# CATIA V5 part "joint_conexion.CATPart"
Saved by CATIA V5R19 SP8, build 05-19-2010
Part number: joint_conexion
Revision: ANY
Definition: UNKNOWN
Nomenclature: 12
Source: Unknown
Bounding box of the stored display mesh (mm): x 0 to 6, y -6 to 6, z 0 to 13
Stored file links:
  D:\Documents\1_Travail\2- 2I2D\1 - Cours et TD\2- TD\3-TD Assemblage\Pompe AirMan\joint_conexion.CATPart
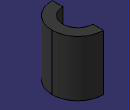
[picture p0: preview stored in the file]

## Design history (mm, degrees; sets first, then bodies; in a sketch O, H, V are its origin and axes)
Body1 "Enlèv. mat.-Extru.1" (main body)
  Solid1: solid without history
